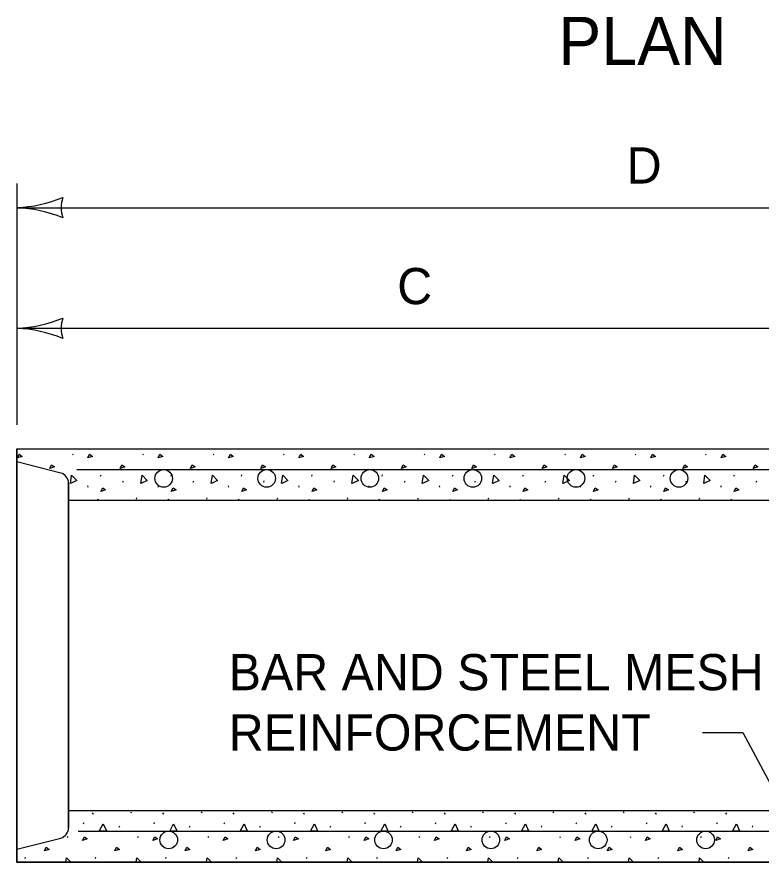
# Model space of a CAD drawing. Extents: x 49991.4 to 50021, y 49987.6 to 50011.4.
# Drawn here: x 50000.684 to 50001.918, y 49995.4 to 49996.801 of the extents above; entities that cross this region are included whole.
import ezdxf

# ---------------------------------------------------------------- set-up
doc = ezdxf.new("R2010")
doc.units = 0
for name, color, linetype in [('Level 1', 7, 'Continuous'), ('Level 2', 7, 'Continuous'), ('Level 3', 7, 'Continuous')]:
    doc.layers.add(name, color=color, linetype=linetype)

msp = doc.modelspace()

# ---------------------------------------------------------------- linework, layer by layer
at = {"layer": 'Level 1'}
for p, q in [((50000.6836, 49996.0847), (50000.6836, 49995.3998)), ((50000.6836, 49996.0847), (50001.9962, 49996.0847)), ((50000.6836, 49996.0847), (50000.6836, 49995.3998)), ((50000.6836, 49995.3998), (50000.6836, 49996.0847)), ((50000.684, 49996.0829), (50000.6847, 49996.0845)), ((50000.7757, 49996.0761), (50000.7767, 49996.0747)), ((50000.8924, 49996.0761), (50000.8934, 49996.0747)), ((50001.0091, 49996.0761), (50001.0101, 49996.0747)), ((50001.1258, 49996.0761), (50001.1268, 49996.0747)), ((50001.2425, 49996.0761), (50001.2435, 49996.0747)), ((50001.3592, 49996.0761), (50001.3602, 49996.0747)), ((50001.4759, 49996.0761), (50001.4768, 49996.0747)), ((50001.5926, 49996.0761), (50001.5935, 49996.0747)), ((50001.7092, 49996.0761), (50001.7102, 49996.0747)), ((50001.8259, 49996.0761), (50001.8269, 49996.0747)), ((50000.6836, 49996.0632), (50000.6836, 49995.4213)), ((50000.7562, 49996.0448), (50000.6836, 49996.0632)), ((50000.7562, 49996.0448), (50000.6836, 49996.0632)), ((50000.7562, 49996.0448), (50000.6836, 49996.0632)), ((50000.7562, 49996.0448), (50000.6836, 49996.0632)), ((50000.8225, 49996.0398), (50000.8235, 49996.042)), ((50000.9392, 49996.0398), (50000.9402, 49996.042)), ((50001.0559, 49996.0398), (50001.0569, 49996.042)), ((50001.1726, 49996.0398), (50001.1735, 49996.042)), ((50001.2893, 49996.0398), (50001.2902, 49996.042)), ((50001.406, 49996.0398), (50001.4069, 49996.042)), ((50001.5226, 49996.0398), (50001.5236, 49996.042)), ((50001.6393, 49996.0398), (50001.6403, 49996.042)), ((50001.756, 49996.0398), (50001.757, 49996.042)), ((50001.8727, 49996.0398), (50001.8737, 49996.042)), ((50000.7692, 49995.4563), (50000.7692, 49996.0282)), ((50000.7692, 49996.0282), (50000.7692, 49995.4854)), ((50000.8008, 49996.0237), (50000.801, 49996.0215)), ((50000.8595, 49996.0299), (50000.8605, 49996.032)), ((50000.9175, 49996.0237), (50000.9177, 49996.0215)), ((50000.9762, 49996.0299), (50000.9772, 49996.032)), ((50001.0341, 49996.0237), (50001.0344, 49996.0215)), ((50001.0929, 49996.0299), (50001.0939, 49996.032)), ((50001.1508, 49996.0237), (50001.1511, 49996.0215)), ((50001.2096, 49996.0299), (50001.2106, 49996.032)), ((50001.2675, 49996.0237), (50001.2678, 49996.0215)), ((50001.3263, 49996.0299), (50001.3273, 49996.032)), ((50001.3842, 49996.0237), (50001.3845, 49996.0215)), ((50001.443, 49996.0299), (50001.444, 49996.032)), ((50001.5009, 49996.0237), (50001.5011, 49996.0215)), ((50001.5597, 49996.0299), (50001.5606, 49996.032)), ((50001.6176, 49996.0237), (50001.6178, 49996.0215)), ((50001.6764, 49996.0299), (50001.6773, 49996.032)), ((50001.7343, 49996.0237), (50001.7345, 49996.0215)), ((50001.7931, 49996.0299), (50001.794, 49996.032)), ((50001.851, 49996.0237), (50001.8512, 49996.0215)), ((50001.9097, 49996.0299), (50001.9107, 49996.032)), ((50000.7692, 49995.999), (50000.7692, 49995.4563)), ((50002.0087, 49995.999), (50000.7692, 49995.999)), ((50000.8174, 49996.0016), (50000.8184, 49996.0001)), ((50000.8184, 49996.001), (50000.8193, 49995.9996)), ((50000.8817, 49996.0016), (50000.8827, 49996.0038)), ((50000.9341, 49996.0016), (50000.9351, 49996.0001)), ((50000.9351, 49996.001), (50000.936, 49995.9996)), ((50000.9984, 49996.0016), (50000.9994, 49996.0038)), ((50001.0508, 49996.0016), (50001.0517, 49996.0001)), ((50001.0517, 49996.001), (50001.0527, 49995.9996)), ((50001.1151, 49996.0016), (50001.1161, 49996.0038)), ((50001.1675, 49996.0016), (50001.1684, 49996.0001)), ((50001.1684, 49996.001), (50001.1694, 49995.9996)), ((50001.2318, 49996.0016), (50001.2327, 49996.0038)), ((50001.2841, 49996.0016), (50001.2851, 49996.0001)), ((50001.2851, 49996.001), (50001.2861, 49995.9996)), ((50001.3485, 49996.0016), (50001.3494, 49996.0038)), ((50001.4008, 49996.0016), (50001.4018, 49996.0001)), ((50001.4018, 49996.001), (50001.4028, 49995.9996)), ((50001.4651, 49996.0016), (50001.4661, 49996.0038)), ((50001.5175, 49996.0016), (50001.5185, 49996.0001)), ((50001.5185, 49996.001), (50001.5195, 49995.9996)), ((50001.5818, 49996.0016), (50001.5828, 49996.0038)), ((50001.6342, 49996.0016), (50001.6352, 49996.0001)), ((50001.6352, 49996.001), (50001.6362, 49995.9996)), ((50001.6985, 49996.0016), (50001.6995, 49996.0038)), ((50001.7509, 49996.0016), (50001.7519, 49996.0001)), ((50001.7519, 49996.001), (50001.7529, 49995.9996)), ((50001.8152, 49996.0016), (50001.8162, 49996.0038)), ((50001.8676, 49996.0016), (50001.8686, 49996.0001)), ((50001.8686, 49996.001), (50001.8695, 49995.9996)), ((50000.7692, 49995.4854), (50000.7692, 49995.4563)), ((50000.7692, 49995.4563), (50000.7692, 49995.4854)), ((50000.7692, 49995.4854), (50002.7668, 49995.4854)), ((50000.7692, 49995.4563), (50000.7692, 49995.4854)), ((50000.8086, 49995.4812), (50000.8096, 49995.4797)), ((50000.8096, 49995.4806), (50000.8106, 49995.4792)), ((50000.873, 49995.4812), (50000.8739, 49995.4834)), ((50000.9253, 49995.4812), (50000.9263, 49995.4797)), ((50000.9263, 49995.4806), (50000.9273, 49995.4792)), ((50000.9896, 49995.4812), (50000.9906, 49995.4834)), ((50001.042, 49995.4812), (50001.043, 49995.4797)), ((50001.043, 49995.4806), (50001.044, 49995.4792)), ((50001.1063, 49995.4812), (50001.1073, 49995.4834)), ((50001.1587, 49995.4812), (50001.1597, 49995.4797)), ((50001.1597, 49995.4806), (50001.1607, 49995.4792)), ((50001.223, 49995.4812), (50001.224, 49995.4834)), ((50001.2754, 49995.4812), (50001.2764, 49995.4797)), ((50001.2764, 49995.4806), (50001.2773, 49995.4792)), ((50001.3397, 49995.4812), (50001.3407, 49995.4834)), ((50001.3921, 49995.4812), (50001.3931, 49995.4797)), ((50001.3931, 49995.4806), (50001.394, 49995.4792)), ((50001.4564, 49995.4812), (50001.4574, 49995.4834)), ((50001.5088, 49995.4812), (50001.5098, 49995.4797)), ((50001.5098, 49995.4806), (50001.5107, 49995.4792)), ((50001.5731, 49995.4812), (50001.5741, 49995.4834)), ((50001.6255, 49995.4812), (50001.6264, 49995.4797)), ((50001.6264, 49995.4806), (50001.6274, 49995.4792)), ((50001.6898, 49995.4812), (50001.6908, 49995.4834)), ((50001.7422, 49995.4812), (50001.7431, 49995.4797)), ((50001.7431, 49995.4806), (50001.7441, 49995.4792)), ((50001.8065, 49995.4812), (50001.8074, 49995.4834)), ((50001.8588, 49995.4812), (50001.8598, 49995.4797)), ((50001.8598, 49995.4806), (50001.8608, 49995.4792)), ((50000.7943, 49995.4631), (50000.7952, 49995.4653)), ((50000.8532, 49995.4575), (50000.8542, 49995.4597)), ((50000.911, 49995.4631), (50000.9119, 49995.4653)), ((50000.9699, 49995.4575), (50000.9709, 49995.4597)), ((50001.0276, 49995.4631), (50001.0286, 49995.4653)), ((50001.0866, 49995.4575), (50001.0876, 49995.4597)), ((50001.1443, 49995.4631), (50001.1453, 49995.4653)), ((50001.2033, 49995.4575), (50001.2043, 49995.4597)), ((50001.261, 49995.4631), (50001.262, 49995.4653)), ((50001.32, 49995.4575), (50001.321, 49995.4597)), ((50001.3777, 49995.4631), (50001.3787, 49995.4653)), ((50001.4367, 49995.4575), (50001.4376, 49995.4597)), ((50001.4944, 49995.4631), (50001.4954, 49995.4653)), ((50001.5534, 49995.4575), (50001.5543, 49995.4597)), ((50001.6111, 49995.4631), (50001.6121, 49995.4653)), ((50001.67, 49995.4575), (50001.671, 49995.4597)), ((50001.7278, 49995.4631), (50001.7288, 49995.4653)), ((50001.7867, 49995.4575), (50001.7877, 49995.4597)), ((50001.8445, 49995.4631), (50001.8454, 49995.4653)), ((50001.9034, 49995.4575), (50001.9044, 49995.4597)), ((50000.6836, 49995.4213), (50000.7562, 49995.4397)), ((50000.767, 49995.442), (50000.768, 49995.4405)), ((50000.8837, 49995.442), (50000.8846, 49995.4405)), ((50001.0004, 49995.442), (50001.0013, 49995.4405)), ((50001.1171, 49995.442), (50001.118, 49995.4405)), ((50001.2337, 49995.442), (50001.2347, 49995.4405)), ((50001.3504, 49995.442), (50001.3514, 49995.4405)), ((50001.4671, 49995.442), (50001.4681, 49995.4405)), ((50001.5838, 49995.442), (50001.5848, 49995.4405)), ((50001.7005, 49995.442), (50001.7015, 49995.4405)), ((50001.8172, 49995.442), (50001.8182, 49995.4405)), ((50000.6836, 49995.3998), (50000.6836, 49995.4213)), ((50000.6971, 49995.4057), (50000.698, 49995.4078)), ((50000.8138, 49995.4057), (50000.8147, 49995.4078)), ((50000.9304, 49995.4057), (50000.9314, 49995.4078)), ((50001.0471, 49995.4057), (50001.0481, 49995.4078)), ((50001.1638, 49995.4057), (50001.1648, 49995.4078)), ((50001.2805, 49995.4057), (50001.2815, 49995.4078)), ((50001.3972, 49995.4057), (50001.3982, 49995.4078)), ((50001.5139, 49995.4057), (50001.5149, 49995.4078)), ((50001.6306, 49995.4057), (50001.6316, 49995.4078)), ((50001.7473, 49995.4057), (50001.7482, 49995.4078)), ((50001.864, 49995.4057), (50001.8649, 49995.4078)), ((50000.6836, 49995.3998), (50002.7668, 49995.3998)), ((50000.6836, 49995.3998), (50002.7668, 49995.3998)), ((50002.7668, 49995.3998), (50000.6836, 49995.3998)), ((50002.7668, 49995.3998), (50000.6836, 49995.3998)), ((50002.7668, 49995.3998), (50000.6836, 49995.3998)), ((50002.7668, 49995.3998), (50000.6836, 49995.3998))]:
    msp.add_line(p, q, dxfattribs=at)
for points in [[(50000.6846, 49996.0698), (50000.6875, 49996.0759), (50000.6924, 49996.0722), (50000.6846, 49996.0698)], [(50000.8013, 49996.0698), (50000.8042, 49996.0759), (50000.8091, 49996.0722), (50000.8013, 49996.0698)], [(50000.918, 49996.0698), (50000.9209, 49996.0759), (50000.9258, 49996.0722), (50000.918, 49996.0698)], [(50001.0347, 49996.0698), (50001.0376, 49996.0759), (50001.0425, 49996.0722), (50001.0347, 49996.0698)], [(50001.1514, 49996.0698), (50001.1543, 49996.0759), (50001.1592, 49996.0722), (50001.1514, 49996.0698)], [(50001.2681, 49996.0698), (50001.271, 49996.0759), (50001.2759, 49996.0722), (50001.2681, 49996.0698)], [(50001.3848, 49996.0698), (50001.3877, 49996.0759), (50001.3926, 49996.0722), (50001.3848, 49996.0698)], [(50001.5014, 49996.0698), (50001.5044, 49996.0759), (50001.5092, 49996.0722), (50001.5014, 49996.0698)], [(50001.6181, 49996.0698), (50001.6211, 49996.0759), (50001.6259, 49996.0722), (50001.6181, 49996.0698)], [(50001.7348, 49996.0698), (50001.7377, 49996.0759), (50001.7426, 49996.0722), (50001.7348, 49996.0698)], [(50001.8515, 49996.0698), (50001.8544, 49996.0759), (50001.8593, 49996.0722), (50001.8515, 49996.0698)], [(50000.738, 49996.0524), (50000.7409, 49996.0585), (50000.7458, 49996.0548), (50000.738, 49996.0524)], [(50000.7828, 49996.0504), (50001.9796, 49996.0504)], [(50000.8547, 49996.0524), (50000.8576, 49996.0585), (50000.8625, 49996.0548), (50000.8547, 49996.0524)], [(50000.9714, 49996.0524), (50000.9743, 49996.0585), (50000.9792, 49996.0548), (50000.9714, 49996.0524)], [(50001.0881, 49996.0524), (50001.091, 49996.0585), (50001.0959, 49996.0548), (50001.0881, 49996.0524)], [(50001.2048, 49996.0524), (50001.2077, 49996.0585), (50001.2126, 49996.0548), (50001.2048, 49996.0524)], [(50001.3215, 49996.0524), (50001.3244, 49996.0585), (50001.3293, 49996.0548), (50001.3215, 49996.0524)], [(50001.4382, 49996.0524), (50001.4411, 49996.0585), (50001.446, 49996.0548), (50001.4382, 49996.0524)], [(50001.5548, 49996.0524), (50001.5578, 49996.0585), (50001.5626, 49996.0548), (50001.5548, 49996.0524)], [(50001.6715, 49996.0524), (50001.6745, 49996.0585), (50001.6793, 49996.0548), (50001.6715, 49996.0524)], [(50001.7882, 49996.0524), (50001.7911, 49996.0585), (50001.796, 49996.0548), (50001.7882, 49996.0524)], [(50001.9049, 49996.0524), (50001.9078, 49996.0585), (50001.9127, 49996.0548), (50001.9049, 49996.0524)], [(50000.7725, 49996.0273), (50000.7744, 49996.0413), (50000.7831, 49996.0323), (50000.7727, 49996.0274)], [(50000.8892, 49996.0273), (50000.8911, 49996.0413), (50000.8998, 49996.0323), (50000.8894, 49996.0274)], [(50001.0059, 49996.0273), (50001.0078, 49996.0413), (50001.0165, 49996.0323), (50001.0061, 49996.0274)], [(50001.1225, 49996.0273), (50001.1245, 49996.0413), (50001.1332, 49996.0323), (50001.1228, 49996.0274)], [(50001.2392, 49996.0273), (50001.2412, 49996.0413), (50001.2499, 49996.0323), (50001.2395, 49996.0274)], [(50001.3559, 49996.0273), (50001.3579, 49996.0413), (50001.3666, 49996.0323), (50001.3562, 49996.0274)], [(50001.4726, 49996.0273), (50001.4745, 49996.0413), (50001.4833, 49996.0323), (50001.4728, 49996.0274)], [(50001.5893, 49996.0273), (50001.5912, 49996.0413), (50001.6, 49996.0323), (50001.5895, 49996.0274)], [(50001.706, 49996.0273), (50001.7079, 49996.0413), (50001.7167, 49996.0323), (50001.7062, 49996.0274)], [(50001.8227, 49996.0273), (50001.8246, 49996.0413), (50001.8333, 49996.0323), (50001.8229, 49996.0274)], [(50000.823, 49996.0143), (50000.8259, 49996.0204), (50000.8308, 49996.0167), (50000.823, 49996.0143)], [(50000.9397, 49996.0143), (50000.9426, 49996.0204), (50000.9475, 49996.0167), (50000.9397, 49996.0143)], [(50001.0564, 49996.0143), (50001.0593, 49996.0204), (50001.0642, 49996.0167), (50001.0564, 49996.0143)], [(50001.1731, 49996.0143), (50001.176, 49996.0204), (50001.1809, 49996.0167), (50001.1731, 49996.0143)], [(50001.2898, 49996.0143), (50001.2927, 49996.0204), (50001.2975, 49996.0167), (50001.2898, 49996.0143)], [(50001.4064, 49996.0143), (50001.4094, 49996.0204), (50001.4142, 49996.0167), (50001.4064, 49996.0143)], [(50001.5231, 49996.0143), (50001.5261, 49996.0204), (50001.5309, 49996.0167), (50001.5231, 49996.0143)], [(50001.6398, 49996.0143), (50001.6427, 49996.0204), (50001.6476, 49996.0167), (50001.6398, 49996.0143)], [(50001.7565, 49996.0143), (50001.7594, 49996.0204), (50001.7643, 49996.0167), (50001.7565, 49996.0143)], [(50001.8732, 49996.0143), (50001.8761, 49996.0204), (50001.881, 49996.0167), (50001.8732, 49996.0143)], [(50000.8203, 49995.451), (50000.8269, 49995.4634), (50000.832, 49995.4519), (50000.8206, 49995.451)], [(50000.937, 49995.451), (50000.9436, 49995.4634), (50000.9487, 49995.4519), (50000.9373, 49995.451)], [(50001.0537, 49995.451), (50001.0603, 49995.4634), (50001.0654, 49995.4519), (50001.054, 49995.451)], [(50001.1704, 49995.451), (50001.177, 49995.4634), (50001.1821, 49995.4519), (50001.1706, 49995.451)], [(50001.2871, 49995.451), (50001.2937, 49995.4634), (50001.2988, 49995.4519), (50001.2873, 49995.451)], [(50001.4038, 49995.451), (50001.4104, 49995.4634), (50001.4155, 49995.4519), (50001.404, 49995.451)], [(50001.5205, 49995.451), (50001.5271, 49995.4634), (50001.5322, 49995.4519), (50001.5207, 49995.451)], [(50001.6372, 49995.451), (50001.6437, 49995.4634), (50001.6489, 49995.4519), (50001.6374, 49995.451)], [(50001.7539, 49995.451), (50001.7604, 49995.4634), (50001.7655, 49995.4519), (50001.7541, 49995.451)], [(50001.8705, 49995.451), (50001.8771, 49995.4634), (50001.8822, 49995.4519), (50001.8708, 49995.451)], [(50000.7853, 49995.4512), (50002.7442, 49995.4512)], [(50000.7926, 49995.4356), (50000.7955, 49995.4417), (50000.8004, 49995.4381), (50000.7926, 49995.4356)], [(50000.9093, 49995.4356), (50000.9122, 49995.4417), (50000.917, 49995.4381), (50000.9093, 49995.4356)], [(50001.0259, 49995.4356), (50001.0289, 49995.4417), (50001.0337, 49995.4381), (50001.0259, 49995.4356)], [(50001.1426, 49995.4356), (50001.1456, 49995.4417), (50001.1504, 49995.4381), (50001.1426, 49995.4356)], [(50001.2593, 49995.4356), (50001.2622, 49995.4417), (50001.2671, 49995.4381), (50001.2593, 49995.4356)], [(50001.376, 49995.4356), (50001.3789, 49995.4417), (50001.3838, 49995.4381), (50001.376, 49995.4356)], [(50001.4927, 49995.4356), (50001.4956, 49995.4417), (50001.5005, 49995.4381), (50001.4927, 49995.4356)], [(50001.6094, 49995.4356), (50001.6123, 49995.4417), (50001.6172, 49995.4381), (50001.6094, 49995.4356)], [(50001.7261, 49995.4356), (50001.729, 49995.4417), (50001.7339, 49995.4381), (50001.7261, 49995.4356)], [(50001.8428, 49995.4356), (50001.8457, 49995.4417), (50001.8506, 49995.4381), (50001.8428, 49995.4356)], [(50000.7293, 49995.4182), (50000.7322, 49995.4243), (50000.7371, 49995.4206), (50000.7293, 49995.4182)], [(50000.846, 49995.4182), (50000.8489, 49995.4243), (50000.8538, 49995.4206), (50000.846, 49995.4182)], [(50000.9627, 49995.4182), (50000.9656, 49995.4243), (50000.9704, 49995.4206), (50000.9627, 49995.4182)], [(50001.0793, 49995.4182), (50001.0823, 49995.4243), (50001.0871, 49995.4206), (50001.0793, 49995.4182)], [(50001.196, 49995.4182), (50001.199, 49995.4243), (50001.2038, 49995.4206), (50001.196, 49995.4182)], [(50001.3127, 49995.4182), (50001.3156, 49995.4243), (50001.3205, 49995.4206), (50001.3127, 49995.4182)], [(50001.4294, 49995.4182), (50001.4323, 49995.4243), (50001.4372, 49995.4206), (50001.4294, 49995.4182)], [(50001.5461, 49995.4182), (50001.549, 49995.4243), (50001.5539, 49995.4206), (50001.5461, 49995.4182)], [(50001.6628, 49995.4182), (50001.6657, 49995.4243), (50001.6706, 49995.4206), (50001.6628, 49995.4182)], [(50001.7795, 49995.4182), (50001.7824, 49995.4243), (50001.7873, 49995.4206), (50001.7795, 49995.4182)], [(50001.8962, 49995.4182), (50001.8991, 49995.4243), (50001.904, 49995.4206), (50001.8962, 49995.4182)], [(50000.7647, 49995.3998), (50000.7657, 49995.4071), (50000.7728, 49995.3998)], [(50000.8814, 49995.3998), (50000.8824, 49995.4071), (50000.8895, 49995.3998)], [(50000.998, 49995.3998), (50000.999, 49995.4071), (50001.0061, 49995.3998)], [(50001.1147, 49995.3998), (50001.1157, 49995.4071), (50001.1228, 49995.3998)], [(50001.2314, 49995.3998), (50001.2324, 49995.4071), (50001.2395, 49995.3998)], [(50001.3481, 49995.3998), (50001.3491, 49995.4071), (50001.3562, 49995.3998)], [(50001.4648, 49995.3998), (50001.4658, 49995.4071), (50001.4729, 49995.3998)], [(50001.5815, 49995.3998), (50001.5825, 49995.4071), (50001.5896, 49995.3998)], [(50001.6982, 49995.3998), (50001.6992, 49995.4071), (50001.7063, 49995.3998)], [(50001.8149, 49995.3998), (50001.8159, 49995.4071), (50001.823, 49995.3998)]]:
    msp.add_lwpolyline(points, dxfattribs=at)
for centre in [(50000.927, 49996.0359), (50001.0979, 49996.0359), (50001.2689, 49996.0359), (50001.4398, 49996.0359), (50001.6108, 49996.0359), (50001.7817, 49996.0359), (50000.9354, 49995.4366), (50001.1135, 49995.4366), (50001.2916, 49995.4366), (50001.4696, 49995.4366), (50001.6477, 49995.4366), (50001.8258, 49995.4366)]:
    msp.add_circle(centre, 0.0146, dxfattribs=at)
for centre, start, end in [((50000.7521, 49996.0282), 0, 75.8703), ((50000.7521, 49995.4563), 284.1107, 0)]:
    msp.add_arc(centre, 0.0171, start, end, dxfattribs=at)
at = {"layer": 'Level 3'}
for p, q in [((50000.6836, 49996.5247), (50000.6836, 49996.1247)), ((50000.6836, 49996.4847), (50002.7668, 49996.4847)), ((50000.6836, 49996.2847), (50001.9962, 49996.2847)), ((50001.8207, 49995.6147), (50001.8874, 49995.6147)), ((50001.8874, 49995.6147), (50001.9727, 49995.4548))]:
    msp.add_line(p, q, dxfattribs=at)
for centre, radius, start, end in [((50000.6721, 49996.7174), 0.233, 272.8273, 292.0772), ((50000.8118, 49996.4847), 0.0548, 162.1388, 197.8612), ((50000.6744, 49996.2626), 0.2223, 67.456, 87.6395), ((50000.6721, 49996.5174), 0.233, 272.8273, 292.0772), ((50000.8118, 49996.2847), 0.0548, 162.1388, 197.8612), ((50000.6744, 49996.0626), 0.2223, 67.456, 87.6395)]:
    msp.add_arc(centre, radius, start, end, dxfattribs=at)

# ---------------------------------------------------------------- texts
at = {"layer": 'Level 2'}
for s, height, p in [('PLAN', 0.08, (50001.5814, 49996.721)), ('D', 0.06, (50001.6949, 49996.5247)), ('C', 0.06, (50001.3144, 49996.3247)), ('BAR AND STEEL MESH', 0.06, (50001.0349, 49995.6847)), ('REINFORCEMENT', 0.06, (50001.0349, 49995.5847))]:
    msp.add_text(s, height=height, dxfattribs=at).set_placement(p)

doc.saveas('drawing.dxf')
